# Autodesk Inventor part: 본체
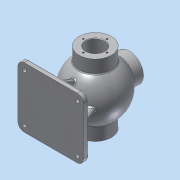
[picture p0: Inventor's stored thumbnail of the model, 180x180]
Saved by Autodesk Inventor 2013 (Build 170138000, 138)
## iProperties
Created: 2018-06
Part Number: 본체
Material: 알루미늄 6061
Document SubType Name: Modeling
Designer: Administrator
Density: 2.71 g/cm^3
Mass: 1509.58 g
Surface Area: 1153.7 cm^2
Volume: 557.041 cm^3
Author: Administrator
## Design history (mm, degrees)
sketch "스케치2"
  geometry: L1 (0, 68)-(0, -68); L2 (0, 68)-(31, 68); L3 (31, -68)-(0, -68); L4 (31, 68)-(31, 42.988); L5 (31, -42.988)-(31, -68); L6 (17.5, 68)-(17.5, 39.278); L7 (17.5, -39.278)-(17.5, -68); A1 r 53 centre (0, 0) between (31, -42.988) and (31, 42.988); A2 r 43 centre (0, 0) between (17.5, -39.278) and (17.5, 39.278); 2 further points
  constraints: 14 end point, 5 perpendicular, 4 point on circle, 3 coincident, 2 centre point, 2 collinear, 2 point on line, 1 midpoint, 1 parallel, 1 vertical
  dimensions: "d4" = 106 diameter of A1; "d5" = 136 distance of L1.start L1.end; "d8" = 62 diameter of L4 L1; "d9" = 86 diameter of A2; "d10" = 35 diameter of L6 L1
revolve "회전1" sketch "스케치2" stored, may be unused: angle "d11" = 90 deg
node "작업 평면1"
sketch "스케치3"
  geometry: L1 (-62.5, -57.5)-(62.5, -57.5); L2 (62.5, -57.5)-(62.5, 57.5); L3 (62.5, 57.5)-(-62.5, 57.5); L4 (-62.5, 57.5)-(-62.5, -57.5); L5 (-62.5, -57.5)-(62.5, 57.5); L6 (62.5, -57.5)-(-62.5, 57.5); 1 further point
  constraints: 12 end point, 2 midpoint, 2 parallel, 1 horizontal, 1 perpendicular
  dimensions: "d13" = 125 distance of L3.end L2.end; "d14" = 115 distance of L2.end L1.end
extrude "돌출1" join sketch "스케치3" distance "d15" = 10; taper "d16" = 0 deg
fillet "모깎기1" dims "d17" = 12
hole "구멍1" diameter "d20" = 8; stored, may be unused: countersink angle "d24" = 90 deg, drill point angle "d26" = 0 deg; dims "d21" = 6, "d22" = 12, "d23" = 3, "d25" = 10, "d96" = 10, "d97" = 10
sketch "스케치4"
  geometry: L1 (-4, -4)-(4, -4); L2 (4, -4)-(4, 4); L3 (4, 4)-(-4, 4); L4 (-4, 4)-(-4, -4); L5 (-4, -4)-(4, 4); L6 (4, -4)-(-4, 4); 1 further point
  constraints: 12 end point, 2 midpoint, 2 parallel, 1 horizontal, 1 perpendicular
  dimensions: "d27" = 8 distance of L3.end L2.end; "d28" = 8 distance of L2.end L1.end
extrude "돌출2" join sketch "스케치4" stored distance "d29" = 10; taper "d30" = 0 deg
sketch "스케치5"
  geometry: L1 (52.5, -75)-(45.715, -58.208); L2 (62.5, -75)-(62.5, -85) reference; L3 (50.5, -75)-(62.5, -75) reference; 1 further point
  constraints: 2 end point, 1 point on line
  dimensions: "d31" = 22 deg angle of L2 L1; "d32" = 10 distance of L2.start L1.start
feature "리브1" sketch "스케치5" dims "d33" = 1, "d34" = 8, "d35" = 0, "d36" = 0, "d37" = 1, "d38" = 1
sketch "스케치6"
  geometry: L1 (-75, -47.5)-(-58.277, -40.743); L2 (-85, -57.5)-(-75, -57.5) reference; L3 (-75, -45.5)-(-75, -57.5) reference; 1 further point
  constraints: 2 end point, 1 point on line
  dimensions: "d39" = 22 deg angle of L2 L1; "d40" = 10 distance from line of L2 L1.start
feature "리브2" sketch "스케치6" dims "d41" = 1, "d42" = 8, "d43" = 0, "d44" = 0, "d45" = 1, "d46" = 1
fillet "모깎기2" dims "d47" = 3
fillet "모깎기3" dims "d48" = 3
fillet "모깎기4" dims "d49" = 3
node "작업 평면2"
sketch "스케치7"
  geometry: C1 r 27 at (0, 0); 1 further point
  constraints: 1 centre point, 1 coincident
  dimensions: "d51" = 54 diameter of C1
extrude "돌출3" join sketch "스케치7" stored distance "d52" = 10; taper "d53" = 0 deg
hole "구멍2" diameter "d56" = 26; stored, may be unused: countersink angle "d60" = 90 deg, drill point angle "d62" = 0 deg; dims "d54" = 10, "d55" = 10, "d57" = 6, "d58" = 4, "d59" = 2, "d61" = 8
chamfer "모따기1" distance "d63" = 1; stored, may be unused: second distance "d64" = 2, angle "d65" = 45 deg
sketch "스케치8"
  geometry: C1 r 27 at (0, 0) reference; 1 further point
  constraints: 1 vertical alignment
  dimensions: "d66" = 20 distance of C1.centre point (0, 20)
hole "구멍3" sketch "스케치8" at (0, 20) diameter "d67" = 3.242; stored, may be unused: countersink angle "d71" = 90 deg, drill point angle "d73" = 118 deg; dims "d68" = 9, "d69" = 4, "d70" = 2, "d72" = 11
node "작업 평면3"
sketch "스케치13"
  geometry: C1 r 31 at (0, 0) reference; 1 further point
  constraints: 1 vertical alignment
  dimensions: "d107" = 22.5 distance of C1.centre point (0, 22.5)
hole "구멍6" sketch "스케치13" at (0, 22.5) diameter "d108" = 3.242; stored, may be unused: countersink angle "d112" = 90 deg, drill point angle "d114" = 118 deg; dims "d109" = 12, "d110" = 4, "d111" = 2, "d113" = 15
sketch "스케치14"
  geometry: C1 r 31 at (0, 0) reference; 1 further point
  constraints: 1 vertical alignment
  dimensions: "d115" = 24 distance of C1.centre point (0, 24)
hole "구멍7" sketch "스케치14" at (0, 24) diameter "d116" = 3.242; stored, may be unused: countersink angle "d120" = 90 deg, drill point angle "d122" = 118 deg; dims "d117" = 16, "d118" = 4, "d119" = 2, "d121" = 19
sketch "스케치11"
  geometry: L1 (0, -27)-(0, 27) reference; 2 further points
  constraints: 1 other
  dimensions: "d98" = 10 distance from line of L1 point (10, 0); "d99" = 27 vertical distance of L1.start point (10, 0)
feature "엠보싱1" sketch "스케치11" dims "d100" = 0.5, "d101" = 0
fillet "모깎기5" dims "d102" = 3
node "작업 평면4"
sketch "스케치12"
  geometry: C1 r 18.5 at (0, 0); 1 further point
  constraints: 1 centre point, 1 coincident
  dimensions: "d104" = 37 diameter of C1
extrude "돌출4" cut sketch "스케치12" distance "d105" = 1.75; taper "d106" = 0 deg
node "솔리드1"
mirror "대칭1"
mirror "대칭2"
mirror "대칭3"
mirror "대칭4"
pattern_circular "원형 패턴1" dims angle "d75" = 360 deg
pattern_circular "원형 패턴3" dims angle "d124" = 360 deg
other parameters: "d6" = 62, "d12" = -85, "d103" = -16
